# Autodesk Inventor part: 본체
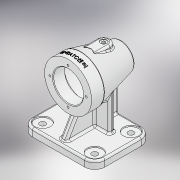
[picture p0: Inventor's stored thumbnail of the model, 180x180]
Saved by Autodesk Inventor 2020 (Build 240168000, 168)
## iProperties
Created: 2024-12
Part Number: 본체
Material: 알루미늄 6061
Document SubType Name: Modeling
Designer: 1강의실14
Mass: 739.312 g
Surface Area: 674.062 cm^2
Volume: 273.819 cm^3
Density: 2.7 g/cm^3
Appearance: 알루미늄 - 평지
Author: 1강의실14
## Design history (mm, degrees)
sketch "스케치1"
  geometry: L1 (37, -28)-(0, -28); L2 (0, -28)-(0, 56); L3 (0, 56)-(37, 56); L4 (37, 56)-(37, -28); L5 (37, 56)-(37, 36); L6 (37, 36)-(21, -28); L7 (21.096, -7)-(32.346, 38); L8 (23.5, 56)-(23.5, 38); L9 (23.5, 38)-(32.346, 38); L10 (21.096, -7)-(17.5, -7); L11 (17.5, -7)-(17.5, -17); L12 (17.5, -17)-(15.5, -17); L13 (15.5, -17)-(15.5, -20); L14 (15.5, -20)-(0, -20); L15 (21, -28)-(0, -28); L16 (37, 56)-(23.5, 56); 1 further point
  constraints: 32 end point, 5 perpendicular, 5 point on line, 4 horizontal, 2 parallel, 1 collinear, 1 vertical
  dimensions: "d0" = 74 diameter of L4 L2; "d1" = 84 distance of L1.end L2.end; "d2" = 56 distance from line of point (0, 0) L3; "d3" = 20 distance of L3.end L5.end; "d4" = 42 diameter of L6.end L2; "d5" = 5 distance between parallel lines of L6 L7; "d6" = 35 diameter of L11 L2; "d8" = 31 diameter of L13 L2; "d9" = 3 distance between parallel lines of L12 L14; "d10" = 10 distance between parallel lines of L10 L12; "d11" = 18 distance from line of L8.start L9; "d12" = 47 diameter of L8 L2; "d13" = 45 distance between parallel lines of L9 L10
revolve "회전1" sketch "스케치1" stored, may be unused: angle "d14" = 90 deg
sketch "스케치2" dims "d15" = 57
  geometry: C1 r 23.5 at (0, 0) reference; 3 further points
  constraints: 2 vertical alignment, 1 coincident, 2 other
hole "구멍1" sketch "스케치2" at (0, 28.5) diameter "d16" = 3.242; stored, may be unused: countersink angle "d20" = 90 deg, drill point angle "d22" = 120 deg; dims "d17" = 8, "d18" = 4, "d19" = 2, "d21" = 10
node "작업 평면1"
sketch "스케치3"
  geometry: L1 (-37, 56)-(37, 56) reference; L2 (10, 0)-(10, 29.345); L3 (10, 29.345)-(-10, 29.345); L4 (-10, 0)-(-10, 29.345); A1 r 10 centre (0, 0) between (10, 0) and (-10, 0); 1 further point
  constraints: 6 end point, 2 perpendicular, 2 point on circle, 2 tangent, 1 centre point, 1 coincident, 1 vertical
  dimensions: "d27" = 20 diameter of A1; "d28" = 56 distance from line of L1 A1.centre
extrude "돌출1" join sketch "스케치3" distance "d29" = 9.12908; taper "d30" = 0 deg
sketch "스케치11"
  geometry: L1 (-23.5, 38)-(23.5, 38) reference; L2 (-32.346, 38)-(32.346, 38) reference; L3 (0, 38)-(-32.346, 38); L4 (-21.096, -7)-(-32.346, 38) reference; L5 (-21.096, -7)-(0, -7); L6 (-17.5, -7)-(17.5, -7) reference; L7 (0, -7)-(0, 38); L8 (-37, 36)-(37, 36) reference; 3 further points
  constraints: 6 end point, 2 midpoint, 1 collinear, 1 perpendicular, 1 point on line
revolve "회전2" sketch "스케치11" stored, may be unused: angle "d91" = 90 deg
sketch "스케치4"
  geometry: C1 r 5 at (0, 0); A1 r 10 centre (0, 0) between (10, 0) and (-10, 0) reference; 1 further point
  constraints: 1 centre point, 1 coincident
  dimensions: "d31" = 10 diameter of C1
extrude "돌출2" cut sketch "스케치4" distance "d32" = 1; taper "d33" = 0 deg
sketch "스케치5"
  geometry: C1 r 5 at (0, 0) reference; 2 further points
  constraints: 1 coincident
hole "구멍2" sketch "스케치5" at (0, 0) diameter "d34" = 5.1881; stored, may be unused: countersink angle "d38" = 90 deg, drill point angle "d40" = 120 deg; dims "d35" = 12, "d36" = 4, "d37" = 2, "d39" = 23
node "작업 평면2"
sketch "스케치6"
  geometry: L1 (57, -18)-(-57, -18); L2 (-57, -18)-(-57, 71); L3 (-57, 71)-(57, 71); L4 (57, 71)-(57, -18); L5 (-21, -28)-(21, -28) reference; 1 further point
  constraints: 8 end point, 2 parallel, 1 horizontal, 1 perpendicular
  dimensions: "d42" = 99 distance between parallel lines of L5 L3; "d43" = 89 distance of L1.end L2.end; "d44" = 114 distance of L2.end L3.end; "d45" = 57 distance from line of point (0, 0) L4
extrude "돌출3" join sketch "스케치6" distance "d46" = 12; taper "d47" = 0 deg
sketch "스케치7"
  geometry: L1 (57, 18)-(-57, 18) reference; 5 further points
  constraints: 2 horizontal alignment, 2 vertical alignment
  dimensions: "d48" = 16 distance from line of L1 point (41, 2); "d49" = 82 distance of point (41, 2) point (-41, 2); "d50" = 41 horizontal distance of point (0, 0) point (-41, 2); "d51" = 57 distance of point (41, -55) point (41, 2)
hole "구멍3" sketch "스케치7" at (41, 2), (-41, 2), (-41, -55), (41, -55) diameter "d52" = 9; stored, may be unused: countersink angle "d56" = 90 deg, drill point angle "d58" = 120 deg; dims "d53" = 12, "d54" = 24, "d55" = 2, "d57" = 23
sketch "스케치8"
  geometry: L1 (-28, -11)-(28, -11); L2 (28, -11)-(28, -19); L3 (28, -19)-(-28, -19); L4 (-28, -19)-(-28, -11); L5 (-5, 18)-(5, 18); L6 (5, 18)-(5, -64); L7 (5, -64)-(-5, -64); L8 (-5, -64)-(-5, 18); L9 (57, 18)-(-57, 18) reference; L10 (-57, -71)-(57, -71) reference; 1 further point
  constraints: 16 end point, 4 parallel, 2 horizontal, 2 perpendicular, 1 collinear
  dimensions: "d59" = 56 distance of L2.end L3.end; "d60" = 8 distance of L1.end L2.end; "d61" = 10 distance of L6.end L7.end; "d62" = 5 distance from line of point (0, 0) L8; "d63" = 29 distance between parallel lines of L9 L1; "d64" = 28 distance from line of point (0, 0) L4; "d65" = 7 distance between parallel lines of L10 L7
extrude "돌출4" join sketch "스케치8" stored distance "d66" = 56; taper "d67" = 0 deg
extrude "돌출5" join sketch "스케치8" stored distance "d68" = 56; taper "d69" = 0 deg
sketch "스케치9"
  geometry: L1 (-37, 56)-(-37, 36) reference; L2 (-37, 44.947)-(-70, 64); L3 (-70, 67)-(-70, 43) reference; L4 (-82, 71)-(-70, 71) reference; L5 (-70, -18)-(-70, 71) reference; 1 further point
  constraints: 2 end point, 2 point on line
  dimensions: "d70" = 7 distance from line of L4 L2.end; "d72" = 60 deg angle of L3 L2
feature "리브1" sketch "스케치9" dims "d73" = 1, "d74" = 10, "d75" = 0, "d76" = 0, "d77" = 1, "d78" = 1
fillet "모깎기1" dims "d79" = 3
node "작업 평면4"
sketch "스케치10"
  geometry: L1 (-37, 10)-(37, 10) reference; 2 further points
  constraints: 1 vertical alignment, 1 other
  dimensions: "d80" = 9 distance from line of L1 point (0, 1)
feature "엠보싱1" sketch "스케치10" dims "d0" = 74, "d1" = 84, "d2" = 56, "d3" = 20, "d4" = 42, "d5" = 5, "d6" = 35, "d8" = 31, "d9" = 3, "d10" = 10, "d11" = 18, "d12" = 47, "d13" = 45, "d81" = 0.5, "d82" = 0
chamfer "모따기1" distance "d83" = 1; stored, may be unused: second distance "d84" = 2, angle "d85" = 45 deg
fillet "모깎기2" dims "d86" = 16
fillet "모깎기3" dims "d87" = 5
fillet "모깎기4" dims "d88" = 3
fillet "모깎기5" dims "d89" = 3
fillet "모깎기6" dims "d90" = 3
fillet "모깎기7" dims "d92" = 0.3
node "솔리드1"
pattern_circular "원형 패턴1" dims angle "d24" = 360 deg
feature "A9D066F2-1C7D-4E18-AEED-F7BC21143FA4" dims "d52" = 9, "d53" = 12, "d54" = 24, "d55" = 2, "d56" = 90 deg, "d57" = 23, "d58" = 120 deg
other parameters: "d26" = 33, "d41" = -82
